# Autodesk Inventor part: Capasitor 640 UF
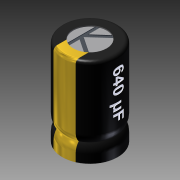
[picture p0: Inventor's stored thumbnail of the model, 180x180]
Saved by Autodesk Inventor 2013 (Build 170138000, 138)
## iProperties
Company: Autodesk Inc.
Created: 2005-12
Part Number: Capasitor 640 UF
Document SubType Name: Modeling
Designer: Autodesk Inc.
Density: 1 g/cm^3
Mass: 0.154067 g
Surface Area: 1.66526 cm^2
Volume: 0.154067 cm^3
Material: Allgemein
Title: Personal Computer
Author: Autodesk Inc.
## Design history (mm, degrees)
sketch "Sketch1"
  geometry: L1 (0, 3.5)-(0, -3.5) reference; L2 (-3.5, 0)-(3.5, 0) reference; C1 r 2.5 at (0, 0)
  constraints: 2 midpoint, 1 centre point
  dimensions: "d0" = 5 diameter of C1
extrude "Extrusion1" new body sketch "Sketch1" distance "d1" = 8; taper "d2" = 0 deg
revolve "Revolution1" stored, may be unused: angle "d19" = 90 deg
sketch "Sketch2"
  geometry: C1 r 2.5 at (0, 0) reference; C2 r 1.5 at (0, 0)
  constraints: 1 centre point, 1 coincident
  dimensions: "d3" = 1 radial gap between concentric circles of C2 C1
extrude "Extrusion2" cut sketch "Sketch2" distance "d4" = 0.1; taper "d5" = 0 deg
sketch "Sketch3"
  geometry: L1 (-0.806, 1.405)-(-0.525, 1.405); L2 (-0.525, 1.405)-(-0.525, -1.405); L3 (-0.525, -1.405)-(-0.806, -1.405); L4 (-0.806, -1.405)-(-0.806, 1.405); L5 (-0.525, -0.051)-(-0.732, 0.181); L6 (-0.732, 0.181)-(0.679, 1.442); L7 (0.679, 1.442)-(0.886, 1.21); L8 (0.886, 1.21)-(-0.525, -0.051); L9 (-0.525, -0.051)-(-0.692, -0.3); L10 (-0.692, -0.3)-(0.86, -1.342); L11 (0.86, -1.342)-(1.027, -1.093); L12 (1.027, -1.093)-(-0.525, -0.051); A1 r 1.5 centre (0, 0) between (1.027, -1.093) and (0.886, 1.21) reference
  constraints: 24 end point, 6 parallel, 4 point on circle, 3 perpendicular, 1 horizontal, 1 point on line
extrude "Extrusion3" cut sketch "Sketch3" distance "d6" = 0.05; taper "d7" = 0 deg
fillet "Fillet1" dims "d8" = 0.3
split "Split1"
workplane "Work Plane1"
sketch "Sketch4"
  geometry: L1 (-7.128, 0.625)-(8.48, 0.625); L2 (8.48, 0.625)-(8.48, -3.214); L3 (8.48, -3.214)-(-7.128, -3.214); L4 (-7.128, -3.214)-(-7.128, 0.625)
  constraints: 2 other
emboss "Emboss1" sketch "Sketch4" dims "d10" = 0.05, "d11" = 0
body "Solid1"
sketch "Sketch5"
  geometry: L1 (0, -4.1)-(0, 3.6) reference; L2 (-1, -1.118)-(-1, -3); L3 (-1, -3)-(1, -3); L4 (1, -3)-(1, -1.118); A1 r 1.5 centre (0, 0) between (-1, -1.118) and (1, -1.118) reference; 3 further points
  constraints: 6 end point, 2 parallel, 2 point on circle, 1 coincident, 1 perpendicular, 1 point on line, 1 vertical alignment, 2 other
  dimensions: "d20" = 2 distance of L2.end L3.end; "d21" = 0.5 distance from line of L3 point (0, -2.5)
sketch "Sketch6"
  geometry: L1 (0, 9.6)-(0, -1.6) reference; L2 (2.5, 0)-(2.5, 8) reference; L3 (2.5, 2.25)-(2.5, 0.75); L4 (2.5, 1.5)-(2.25, 1.5); L5 (-2.5, 0)-(2.5, 0) reference; A1 r 1.25 centre (1.25, 2.25) between (2.25, 1.5) and (2.5, 2.25); A2 r 1.25 centre (1.25, 0.75) between (2.5, 0.75) and (2.25, 1.5); 1 further point
  constraints: 4 end point, 4 point on circle, 2 centre point, 2 point on line, 2 tangent, 1 collinear, 1 horizontal, 1 midpoint
  dimensions: "d16" = 1.5 distance of L3.start L3.end; "d17" = 1.5 distance between parallel lines of L5 L4; "d18" = 0.25 distance of L4.start L4.end
